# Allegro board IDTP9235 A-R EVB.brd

Outline 40 x 65 mm; copper layers: TOP, TOP_1, BOTTOM. Coordinates in mm from the lower left corner of the outline.
Outline path: 0,65 40,65 40,0 0,0 0,65

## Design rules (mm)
nets with their own width: min track width 0.102; nets GND_POWER

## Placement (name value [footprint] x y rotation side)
A4  PTH_TP  [TP_40]  38.44 7.71 0 top
B2  PTH_TP  [TP_40]  38.44 10.25 0 top
B3  PTH_TP  [TP_40]  38.44 12.79 0 top
BUZ  PTH_TP  [TP_40]  38.44 17.87 0 top
C1  22nF  [0402]  15.02 16.04 180 top
C2  1uF  [0402]  13.47 14.87 180 top
C3  220pF  [0402]  15.38 17.36 90 top
C4  220pF  [0402]  17.17 16.29 0 top
C5  5.6nF  [0402]  13.22 17.36 270 top
C6  6.8nF  [0402]  18.48 16.74 270 top
C7  1uF/10V  [0402]  12.89 2.2 0 top
C8  10uF/10V  [0402]  21.17 16.75 90 top
C9  0.1uF  [0402]  20.3 16.73 90 top
C10  10uF/10V  [0603]  28.55 21.1 0 top
C11  10uF/10V  [0603]  28.46 15.89 0 top
C12  0.1uF  [0402]  28.84 19.75 0 top
C13  0.1uF  [0402]  16.37 7.86 180 top
C14  1uF  [0402]  16.57 14.06 270 top
C15  100nF/50V  [1206]  11.26 20.92 90 top
C16  100nF  [0402]  22.62 16.02 0 top
C17  100nF/50V  [1206]  14.11 20.89 90 top
C18  0.1uF  [0402]  16.57 12.35 90 top
C19  10uF  [0603]  15.1 12.36 90 top
C20  0.1uF  [0402]  13.14 7.81 180 top
C21  10uF  [0603]  12.99 8.98 180 top
C22  NP  [0402]  28.84 17.92 180 top
C23  100nF/50V  [1206]  16.98 20.92 90 top
C24  22nF/25V  [0402]  26.05 19.77 0 top
C25  100nF/50V  [1206]  19.8 20.94 90 top
C26  100nF  [0402]  26.6 12.41 90 top
C27  1uF  [0402]  16.39 10.63 180 top
C28  0.1uF  [0402]  16.37 8.8 180 top
C29  1uF  [0402]  16.37 9.72 180 top
C30  10uF  [0603]  28.46 14.62 0 top
C31  0.1uF  [0402]  28.84 17.01 0 top
C32  NP  [0402]  27.99 22.31 0 top
C33  22nF/25V  [0402]  27.21 24.32 180 top
C34  0.1uF  [0402]  29.14 10.68 90 top
C35  NP  [0402]  20.71 18.02 180 top
C36  NP  [0402]  22.44 22.39 180 top
D1  CMOD3003  [SOD523PD]  10.91 16.6 270 top
D2  LED  [0603_DIODE]  25.66 4.05 270 top
D3  LED  [0603_DIODE]  29.14 4.08 270 top
ENB  PTH_TP  [TP_40]  1.52 15.35 0 top
GND  PTH_TP  [TP_40]  14.36 3.93 0 top
GND1  PTH_TP  [TP_40]  1.52 10.27 0 top
GND2  PTH_TP  [TP_40]  38.44 2.63 0 top
GND3  PTH_TP  [TP_40]  38.44 20.41 0 top
GND_TS  28AWG  [25MIL_TH]  27.92 13.02 0 top
ISNS1  PTH_TP  [28MIL_SMD]  12.08 12.89 0 top
ISNS2  PTH_TP  [28MIL_SMD]  10.73 9.49 0 top
ISNS_IN  PTH_TP  [TP_40]  1.52 20.43 0 top
J1  5P  [USB_MICRO_AB]  20 1.33 0 top
L1  4.7uH  [0603]  12.96 10.28 0 top
L2_1  PTH_TP  [40MIL_50PAD]  22.74 24.07 0 top
L2_2  PTH_TP  [40MIL_50PAD]  15.58 24.14 0 top
LDO18  PTH_TP  [TP_40]  38.42 5.2 0 top
LDO33  PTH_TP  [TP_40]  1.52 2.65 0 top
NOREF  -  []  40 25.01 0 top
NOREF#2  -  [unnamed#2]  38.48 23.48 0 top
NOREF#3  -  []  -116.58 -147.48 0 top
NOREF#4  -  [unnamed#2]  34.67 1.52 0 top
NOREF#5  -  []  30.51 0 0 top
NOREF#6  -  [unnamed#2]  1.52 23.48 0 top
NOREF#7  -  []  0 65 0 top
NOREF#8  -  []  9.49 0.08 0 top
NOREF#9  -  []  0.31 0 90 top
NOREF#10  -  []  0 0 90 top
NOREF#11  -  []  9.48 0 0 top
Q1  FDC654P/SOT23-6  [FDC654P]  11.77 4.99 180 top
Q2  AON7810  [DFN_3X3_DUAL_6LD]  25.26 17.49 270 top
Q3  AON7810  [DFN_3X3_DUAL_6LD]  25.23 22.09 270 top
R1  10k  [0402]  14.23 17.36 270 top
R2  1k  [0402]  17.17 17.39 180 top
R3  220k  [0402]  12.2 17.36 270 top
R4  10  [0402]  13.78 13.5 270 top
R5  10  [0402]  12.84 13.5 90 top
R6  0.02  [0603]  11.03 11.9 90 top
R7  100k  [0402]  11.11 2.2 0 top
R8  1K  [0402]  15.2 14.11 180 top
R9  12  [0402]  22.62 16.88 180 top
R10  NP  [0402]  22.49 18.02 0 top
R11  0  [0402]  24.29 19.77 180 top
R12  12  [0402]  24.72 13.75 270 top
R13  100k  [0402]  28.84 18.86 180 top
R14  12  [0402]  22.44 20.61 180 top
R15  NP  [0402]  22.44 21.53 0 top
R16  12  [0402]  25.64 13.75 270 top
R17  5.1k  [0402]  12.77 16.05 0 top
R18  0  [0402]  25.46 24.32 180 top
R19  100k  [0402]  27.99 23.28 0 top
R20  10k  [0402]  29.14 8.88 270 top
R21  100  [0402]  26.71 9.89 270 top
R22  1K  [0402]  26.81 3.8 90 top
R23  680  [0402]  28 3.77 90 top
R24  NP  [0402]  21.98 6.47 270 top
R25  NP  [0402]  21.09 6.47 270 top
R26  NP  [0402]  24.62 6.47 270 top
R27  NP  [0402]  25.49 6.47 270 top
R28  47k  [0402]  22.87 6.47 90 top
R29  47k  [0402]  20.23 6.47 90 top
R30  47k  [0402]  23.76 6.47 90 top
R31  47k  [0402]  26.35 6.47 90 top
RT1  THERMISTOR 2  [0603]  27.9 10.61 90 top
SCL  PTH_TP  [TP_40]  1.52 5.19 0 top
SDA  PTH_TP  [TP_40]  1.52 7.73 0 top
SS1  Solder_Jumper  [SS3]  13.07 11.65 0 top
TS  PTH_TP  [TP_40]  38.44 15.33 0 top
TS1  28AWG  [25MIL_TH]  27.95 8.24 0 top
U1  P9235A-R  [QFN_40LD_5X5MM_3P75THERM]  20.84 11.88 0 top
VIN_5V  PTH_TP  [TP_40]  1.52 12.81 0 top
VIN_USB  PTH_TP  [TP_40]  14.36 6.47 0 top
VSNS_IN  PTH_TP  [TP_40]  1.52 17.89 0 top

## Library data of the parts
A4 B2 B3 BUZ ENB GND GND1-GND3 ISNS1 ISNS2 ISNS_IN L2_1 L2_2 LDO18 LDO33 SCL SDA TS VIN_5V VIN_USB VSNS_IN = PTH_TP
C1 C5 = C
C2-C4 C6-C36 = CAP NP
D1 = DIODE_1
D2 D3 = LED_0
GND_TS TS1 = PTH
J1 = MICRO USB AB_5
L1 = INDUCTOR
Q1 = IRF6215/TO_2
Q2 Q3 = DMG7430LFG_0
R1-R31 = RESISTOR
RT1 = THERMISTOR 2
SS1 = SolderShort_0
U1 = IDTP9235_7

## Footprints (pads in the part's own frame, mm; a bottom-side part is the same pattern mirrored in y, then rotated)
25MIL_TH
  round 0.889 hole 0.635: 1(0,0)
28MIL_SMD
  round 0.711 smd: 1(0,0)
40MIL_50PAD
  round 1.27 hole 1.016: 1(0,0)
0402
  rect 0.61x0.61 smd: 1(-0.445,0) 2(0.445,0)
0603
  rect 0.635x0.889 smd: 1(-0.762,0) 2(0.762,0)
0603_DIODE
  rect 0.8x0.8 smd: 1(-0.8,0) 2(0.8,0)
1206
  rect 1.4x1.6 smd: 1(-1.5,0) 2(1.5,0)
DFN_3X3_DUAL_6LD
  custom 0.369x0.369 smd: 1(0.859,0.537) 4(-0.859,-0.537)
  rect 0.4x0.58 smd: 2(-0.328,1.36) 3(-0.978,1.36) 5(0.328,-1.36) 6(0.978,-1.36)
FDC654P
  rect 0.7x1 smd: 1(0.95,1.3) 2(0,1.3) 3(-0.95,1.3) 4(-0.95,-1.3) 5(0,-1.3) 6(0.95,-1.3)
QFN_40LD_5X5MM_3P75THERM
  custom 0.062x0.062 smd: 1(-2.418,1.8) 2(-2.418,1.4) 3(-2.418,1) 4(-2.418,0.6) 5(-2.418,0.2) 6(-2.418,-0.2) 7(-2.418,-0.6) 8(-2.418,-1) 9(-2.418,-1.4) 10(-2.418,-1.8) 11(-1.8,-2.418) 12(-1.4,-2.418) 13(-1,-2.418) 14(-0.6,-2.418) 15(-0.2,-2.418) 16(0.2,-2.418) 17(0.6,-2.418) 18(1,-2.418) 19(1.4,-2.418) 20(1.8,-2.418) 21(2.418,-1.8) 22(2.418,-1.4) 23(2.418,-1) 24(2.418,-0.6) 25(2.418,-0.2) 26(2.418,0.2) 27(2.418,0.6) 28(2.418,1) 29(2.418,1.4) 30(2.418,1.8) 31(1.8,2.418) 32(1.4,2.418) 33(1,2.418) 34(0.6,2.418) 35(0.2,2.418) 36(-0.2,2.418) 37(-0.6,2.418) 38(-1,2.418) 39(-1.4,2.418) 40(-1.8,2.418)
  rect 3.75x3.75 smd: 41(0,0)
SOD523PD
  rect 0.8x0.6 smd: 1(-0.55,0) 2(0.55,0)
SS3
  rect 0.254x0.254 smd: 1(-0.889,0) 2(0.889,0)
TP_40
  round 1.524 hole 1.016: 1(0,0)
unnamed#2
  round 1.016 smd: (0,0)
USB_MICRO_AB
  rect 0.4x1.35 smd: 1(-1.3,2.8) 2(-0.65,2.8) 3(0,2.8) 4(0.65,2.8) 5(1.3,2.8)
  oval 1.05x1.25 hole 0.65x0.85: 6(-2.225,3.125) 7(2.225,3.125)
  rect 2.1x1.9 hole 1.5x0.825: 8(4.087,0) 9(-4.087,0)
  rect 1.8x1.9 smd: 10(-1.15,0) 11(1.15,0)

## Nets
GND_POWER: C3.2 C4.1 C5.1 C8.2 C9.2 C10.2 C11.2 C12.2 C13.2 C14.1 C18.1 C19.1 C20.1 C21.1 C22.1 C24.2 C27.2 C28.2 C29.2 C30.2 C31.2 C32.1 C33.1 C34.2 GND.1 GND1.1 GND2.1 GND3.1 GND_TS.1 J1.5 J1.6 J1.7 J1.8 J1.9 J1.10 J1.11(SHIELD) Q2.2(S2) Q3.2(S2) R3.1 R7.1 R8.1 R13.1 R19.1 R28.1 R29.1 R30.1 R31.1 RT1.2 U1.2(GND_S) U1.6(GND_B) U1.28(GND_BRG) U1.35(VSNS_GND) U1.41(EPGND)
VIN_5V: C18.2 C19.2 ISNS2.1 Q1.1 Q1.2 Q1.5 Q1.6 R4.2 R6.1 SS1.2 U1.4(VIN) VIN_5V.1
VIN_LDO: C8.1 C20.2 C21.2 L1.1 SS1.1 U1.8(VIN_LDO) U1.33(VIN_DRV)
VIN_USB: C7.2 C13.1 J1.1 Q1.4 VIN_USB.1
A4: A4.1 U1.17(GPIOA4)
B2: B2.1 U1.22(GPIOB2)
B3: B3.1 U1.23(GPIOB3)
BUZ: R21.2 U1.19(BUZ)
BUZ_TP: BUZ.1 R21.1
ENB: ENB.1 R8.2 U1.1(ENB)
ILIM: R26.1 R30.2 U1.15(ILIM)
ISNS_H: C2.1 R4.1 U1.40(ISNS_H)
ISNS_IN: C6.2 ISNS_IN.1 U1.37(ISNS_IN)
ISNS_L: C2.2 R5.2 U1.39(ISNS_L)
LDO18: C28.1 C29.1 LDO18.1 R24.2 R25.2 R26.2 R27.2 U1.9(VO_18)
LDO33: C27.1 D2.1(ANODE) D3.1(ANODE) LDO33.1 R20.2 U1.7(VO_33) U1.12(VDDIO)
LED_GRN: R23.2 U1.21(LED_GRN)
LED_PAT: R27.1 R31.2 U1.16(LED_PAT)
LED_RED: R22.2 U1.20(LED_RED)
RSVD1: R24.1 R28.2 U1.10(RSVD1)
RSVD2: R25.1 R29.2 U1.11(RSVD2)
SCL: SCL.1 U1.13(SCL)
SDA: SDA.1 U1.14(SDA)
TS: C34.1 R20.1 RT1.1 TS.1 TS1.1 U1.18(TS)
V_BRIDGE: C9.1 C10.1 C11.1 C12.1 C30.1 C31.1 ISNS1.1 Q2.1(D1) Q3.1(D1) R5.1 R6.2 U1.34(VBRG_IN)
VSNS: C5.2 R1.2 R3.2 R17.2
VSNS_IN: C1.1 C3.1 U1.36(VSNS_IN) VSNS_IN.1
N10945: C16.1 U1.31(BST_BRG1)
N10949: C15.1 C16.2 C17.1 C23.1 C25.1 C35.2 Q2.4(D2) Q2.5(S1) R10.2 R11.2 U1.30(SW_BRG1)
N15418: C14.2 U1.3(VO_5)
N61520: C4.2 R2.2 U1.38(ISNS_OUT)
N85909: C26.2 C36.2 L2_1.1 Q3.4(D2) Q3.5(S1) R15.1 R18.2 U1.26(SW_BRG2)
N315180: L1.2 U1.5(SW_B)
N330742: C1.2 R1.1
N332949: C32.2 Q3.3(G2) R16.1 R19.2
N337526: C22.2 Q2.3(G2) R12.1 R13.2
N368946: C15.2 C17.2 C23.2 C25.2 D1.1(A) L2_2.1
N369446: C36.1 Q3.6(G1) R14.1 R15.2
N411524: R9.2 U1.32(GH_BRG1)
N411528: R12.2 U1.29(GL_BRG1)
N411540: R14.2 U1.24(GH_BRG2)
N412617: R16.2 U1.27(GL_BRG2)
N412738: C26.1 U1.25(BST_BRG2)
N417086: C24.1 R11.1
N429702: C33.2 R18.1
N534596: D1.2(C) R17.1
N558172: D2.2(CATHODE) R22.1
N558182: D3.2(CATHODE) R23.1
N579644: C35.1 Q2.6(G1) R9.1 R10.1
N602902: C6.1 R2.1
N8105676: C7.1 Q1.3 R7.2

Pads without a net: J1 2 3 4

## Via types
v1: diameter 0.406, hole 0.203, TOP to BOTTOM, 104 vias
v2: diameter 0.508, hole 0.254, TOP to BOTTOM, 12 vias

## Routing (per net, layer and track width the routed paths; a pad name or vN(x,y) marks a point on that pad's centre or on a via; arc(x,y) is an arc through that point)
GND_POWER: length 22.2
  TOP w0.152: U1.35 21.04,14.65 19.49,16.19 19.49,16.29
  TOP w0.203: v1(19.54,17.03) 19.49,17.08 19.49,17.69 18.98,18.2 16.04,18.2 15.89,18.05 15.62,18.05 C3.2
  TOP w0.254: C8.2 21.14,17.17 v1(20.61,17.17) C9.2 19.68,17.17 v1(19.54,17.03) 19.49,16.98 19.49,16.29 ; v1(29.61,18.86) R13.1 ; C5.1 v1(12.71,17.81) R3.1 ; v1(29.61,17.01) C31.2 ; C3.2 v1(15.38,18.15) ; 19.44,13.28 U1.2 17.89,13.28 17.56,13.6 17.56,14.01 17.07,14.5 C14.1 16.04,14.5 R8.1 ; 20.41,11.68 U1.6 16.8,11.68 C18.1 ; v1(29.61,19.75) C12.2 ; v1(29.61,17.92) C22.1 ; U1.28 v1(23.89,12.87)
  vias: v1(14.29,7.86) v1(14.82,10.61) v1(15.43,10.61) v1(15.45,8.9) v1(15.45,7.86) v1(16.09,11.37) v1(16.72,16.29) v1(18.85,1.33) v1(20.28,7.66) v1(21.15,1.33) v1(25.74,10.3) v1(26.4,6.01) v1(26.49,19.77) v1(27.34,18.8) v1(27.34,18.23) v1(27.34,17.67) v1(27.54,23.38) v1(27.54,22.8) v1(27.54,22.24) v1(27.66,24.32) v1(29.22,15.89) v1(29.22,14.62) v1(29.25,13.63) v1(29.31,21.1) v1(29.3,12.79) v1(29.3,12) v2(19.35,12.49) v2(19.35,11.47) v2(19.35,10.46) v2(20.37,12.49) v2(20.37,11.47) v2(20.37,10.46) v2(21.38,12.49) v2(21.38,11.47) v2(21.38,10.46) v2(22.4,12.49) v2(22.4,11.47) v2(22.4,10.46)
VIN_5V: length 24.2
  TOP w0.254: v1(15.1,13.12) 15.86,13.12 16.18,12.79 C18.2 17.25,12.79 17.57,12.48 U1.4
  TOP w0.508: VIN_5V.1 3.78,10.55 v1(8.44,10.55)
  BOTTOM w0.152: v1(13.78,12.99) 13.14,12.76 11.29,12.76 10.81,12.28 10.81,11.29 10.96,11.14 v1(11.06,11.14)
  BOTTOM w0.254: v1(15.1,13.12) 14.51,13.12 13.78,12.38 11.39,12.38 11.14,12.13 11.14,11.21 v1(11.06,11.14)
  BOTTOM w0.508: v1(8.44,10.55) 10.48,10.55 v1(11.06,11.14)
VIN_LDO: length 26.3
  TOP w0.203: U1.33 21.84,14.89 21,15.72 21,15.98 v1(21.02,15.99) ; U1.8 17.78,10.88 v1(17.64,10.83)
  TOP w0.254: v1(21.02,15.99) 21.02,16.28 C8.1 ; v1(10.3,15.48) 10.3,12.28 10.27,12.25 10.78,11.75 12.08,11.75 SS1.1
  BOTTOM w0.203: 17.11,11.19 17.46,10.83 v1(17.64,10.83)
  BOTTOM w0.254: v1(10.3,15.48) 10.55,15.74 19.03,15.74 19.24,15.53 20.53,15.53 20.99,15.99 v1(21.02,15.99) ; v1(12.23,8.95) 14.49,8.95 16.72,11.19 17.11,11.19
VIN_USB: length 4.4
  TOP w0.254: Q1.4 12.72,5.57 13.35,4.94 13.35,2.46 C7.2
A4: length 22.4
  TOP w0.127: U1.17 21.44,8.99 22.51,7.91 23.68,7.91 23.94,7.66 25.33,7.66 v1(25.46,7.56) ; v1(31.28,4.1) 35.52,4.1 38.44,7.02 A4.1
  BOTTOM w0.127: v1(31.28,4.1) 27.09,4.1 25.69,5.5 25.69,7.3 v1(25.46,7.56)
B2: length 18
  TOP w0.127: B2.1 38.07,10.25 34.8,6.97 v1(31.3,6.97)
  TOP w0.203: U1.22 24.12,10.48 25.89,8.7 v1(25.89,8.62)
  BOTTOM w0.127: v1(31.3,6.97) 31.13,7.15 27.37,7.15 v1(25.89,8.62)
B3: length 19.5
  TOP w0.127: B3.1 38.44,11.98 34.05,7.58 31.3,7.58 v1(31.28,7.61)
  TOP w0.203: U1.23 23.3,10.83 24.32,10.83 26.48,8.67 v1(26.55,8.67)
  BOTTOM w0.127: v1(26.55,8.67) 26.55,8.5 27.65,7.4 31.07,7.4 v1(31.28,7.61)
BUZ: length 6.8
  TOP w0.127: R21.2 26.87,9.45 26.96,9.36 26.96,8.47 26.71,8.22 24.19,8.22 23.99,8.42 22.84,8.42 22.18,9.08 22.18,9.4 U1.19
BUZ_TP: length 15.4
  TOP w0.127: BUZ.1 38.44,16.85 32.17,10.58 v1(31.3,10.58)
  BOTTOM w0.127: v1(31.3,10.58) 26.96,10.58 v1(26.73,10.35)
  vias: v1(26.73,11.11)
ENB: length 19.2
  TOP w0.127: R8.2 14.74,14.12 14.74,14.49 14.87,14.62 15.63,14.62 16.01,15 17.38,15 18.2,14.19 18.2,13.8 18.32,13.68 U1.1 ; v1(8.42,13.58) 3.29,13.58 ENB.1
  BOTTOM w0.127: v1(14.77,14.09) 14.26,13.58 v1(8.42,13.58)
ILIM: length 5.4
  TOP w0.127: U1.15 20.69,9.41 20.69,8.93 22.21,7.4 23.4,7.4 23.76,7.05 R30.2
  TOP w0.254: R30.2 R26.1
ISNS_H: length 6.1
  TOP w0.127: U1.40 19.04,14.59 18.35,15.28 13.75,15.28 13.68,15.2 13.68,15.13
ISNS_IN: length 21.9
  TOP w0.127: v1(8.39,17.13) 4.82,17.13 ISNS_IN.1 ; v1(18.48,16.29) 18.55,16.29 20.24,14.61 U1.37
  BOTTOM w0.127: v1(8.39,17.13) 14.34,17.13 14.87,17.67 17.1,17.67 v1(18.48,16.29)
ISNS_L: length 7.1
  TOP w0.127: U1.39 19.44,14.62 18.53,15.53 13.55,15.53 13.29,15.28 13.29,15.14
LDO18: length 35.1
  TOP w0.127: C28.1 16.92,8.8 17.41,8.31 17.41,7.61 18.41,6.61 v1(18.5,6.44)
  TOP w0.203: C29.1 17.16,9.72 17.91,10.48 U1.9
  TOP w0.254: C29.1 C28.1 ; R24.2 R25.2 ; v1(31.28,3.14) 36.36,3.14 LDO18.1
  BOTTOM w0.127: 19.57,5.96 19.21,5.96 v1(18.5,6.44) ; 19.57,5.96 21.04,5.96 v1(21.07,5.98) ; 19.57,5.96 19.57,3.09 19.7,2.96 24.85,2.96 25.05,3.16
  BOTTOM w0.254: v1(25.05,5.98) 25.05,3.16 25.08,3.14 v1(31.28,3.14)
LDO33: length 52
  TOP w0.203: v1(19.42,8.78) 19.44,8.8 U1.12 ; C27.1 16.85,10.64 16.85,10.99 17.14,11.28 U1.7 ; v1(18.73,6.92) 18.6,6.92 17.71,7.81 v1(17.71,8.88)
  TOP w0.254: 27.42,5.4 28.62,5.4 D3.1 29.32,5.06 29.32,8.26 R20.2 ; 27.42,5.4 v1(27.42,2.58) ; 27.42,5.4 26.21,5.4 D2.1 ; v1(8.47,1.26) 3.9,1.26 2.51,2.65 LDO33.1
  BOTTOM w0.203: v1(16.85,10.61) 17.71,9.74 v1(17.71,8.88) 17.92,8.67 19.31,8.67 v1(19.42,8.78)
  BOTTOM w0.254: v1(8.47,1.26) 13.88,1.26 15.25,2.63 15.28,2.6 19.21,2.6 ; v1(18.73,6.92) 18.3,6.92 17.99,6.62 17.99,6.29 19.21,5.07 19.21,2.6 ; 19.21,2.6 27.29,2.6 v1(27.42,2.58)
LED_GRN: length 8.3
  TOP w0.203: v1(25.31,8.62) 25.31,8.78 24.01,10.08 U1.21
  TOP w0.254: v1(28,4.92) R23.2
  BOTTOM w0.127: v1(28,4.92) 27.95,5.07 26.96,6.06 26.96,6.82 26.96,7 25.33,8.62 v1(25.31,8.62)
LED_PAT: length 6.7
  TOP w0.127: U1.16 21.04,8.98 22.36,7.66 23.56,7.66 23.81,7.4 25.03,7.4 25.49,6.95 R27.1
  TOP w0.254: R27.1 R31.2
LED_RED: length 8.3
  TOP w0.127: U1.20 22.64,9.01 22.97,8.67 24.72,8.67 v1(24.78,8.62)
  TOP w0.254: v1(26.91,4.84) 26.91,4.34 R22.2
  BOTTOM w0.127: v1(24.78,8.62) 25.36,7.96 25.61,7.96 25.94,7.63 25.94,5.63 26.76,4.81 v1(26.91,4.84)
RSVD1: length 8
  TOP w0.127: v1(19.37,6.49) 19.37,6.85 18.25,7.96
  TOP w0.203: U1.10 18.25,9.9 18.25,7.96
  TOP w0.254: R24.1 R28.2
  BOTTOM w0.127: v1(21.98,6.95) 21.42,6.39 20.69,6.39 20.56,6.26 19.59,6.26 v1(19.37,6.49)
RSVD2: length 4.6
  TOP w0.127: U1.11 19.04,9.01 18.63,8.6 18.63,7.96 19.68,6.91 R29.2
  TOP w0.254: R25.1 R29.2
SCL: length 29.2
  TOP w0.127: v1(8.46,1.85) 5.26,1.85 1.92,5.19 SCL.1
  TOP w0.203: U1.13 19.87,9.42 19.87,8.55 19.29,7.96 v1(19.21,7.96)
  BOTTOM w0.127: v1(8.46,1.85) 8.72,1.59 13.75,1.59 15.12,2.96 18.53,2.96 18.86,3.29 18.86,4.97 17.74,6.08 17.41,6.08 17,6.49 17,7.74 17.38,8.12 19.06,8.12 v1(19.21,7.96)
SDA: length 30.5
  TOP w0.127: v1(8.47,2.45) 6.8,2.45 SDA.1
  TOP w0.203: U1.14 20.24,8.36 v1(20.28,8.32)
  BOTTOM w0.127: v1(20.28,8.32) 20.23,8.37 17.23,8.37 16.75,7.89 16.75,6.34 17.26,5.83 17.61,5.83 18.6,4.84 18.6,3.42 18.4,3.21 15,3.21 13.62,1.84 9.08,1.84 v1(8.47,2.45)
TS: length 20.2
  TOP w0.127: RT1.1 27.42,9.84 27.21,9.64 27.21,8.32 26.86,7.96 24.04,7.96 23.84,8.17 22.67,8.17 21.84,9 U1.18 ; TS.1 38.44,15.18 33.21,9.94 v1(31.38,9.94)
  BOTTOM w0.127: v1(31.38,9.94) 31.35,9.94 31.02,10.28 29.3,10.28 v1(29.19,10.17)
V_BRIDGE: length 7.9
  TOP w0.203: U1.34 21.44,14.81 20.38,15.86 ; C9.1 v1(20.3,16.23)
  TOP w0.254: C9.1 20.38,16.21 20.38,15.86
  BOTTOM w0.203: 21.45,14.75 21.47,14.77 21.47,16.17 21.17,16.47 20.75,16.47 20.69,16.35 v1(20.3,16.23)
  BOTTOM w0.254: v1(23.81,15.23) 23.35,14.77 21.47,14.77
  vias: v1(10.83,14.19) v1(10.98,15.13) v1(11.29,14.57) v1(11.72,15.1) v1(23.81,15.79) v1(24.39,15.79) v1(24.37,15.23)
VSNS: length 2.9
  TOP w0.203: R3.2 C5.2 ; C5.2 R17.2 ; C5.2 R1.2
VSNS_IN: length 25
  TOP w0.127: U1.36 20.58,14.35 20.58,14.67 19.09,16.17 19.09,17.64 18.83,17.9 16.22,17.9 16.09,17.77 16.09,17.12 v1(15.89,16.92) ; v1(8.44,16.27) 3.14,16.27 VSNS_IN.1
  TOP w0.203: C1.1 15.38,16.08 C3.1 v1(15.89,16.92)
  BOTTOM w0.127: v1(8.44,16.27) 8.65,16.07 15.03,16.07 v1(15.89,16.92)
N10945: length 2.2
  TOP w0.203: U1.31 22.64,15.28 22.16,15.76 22.16,16.13 C16.1
N10949: length 6.2
  TOP w0.203: v1(23.06,16.02) 23.12,16.05 23.12,13.81 U1.30 ; C35.2 20.27,18.97 C25.1
  BOTTOM w0.254: v1(23.06,16.02) 23.06,17.97 v1(22.95,18.09)
N15418: length 2.2
  TOP w0.203: C14.2 16.61,13.65 16.93,13.65 17.7,12.88 U1.3
N61520: length 5.2
  TOP w0.127: R2.2 16.72,16.96 16.88,16.8 17.43,16.8 17.61,16.63 C4.2 17.61,15.96 17.79,15.79 18.68,15.79 19.84,14.63 U1.38
N85909: length 14
  TOP w0.203: U1.26 25,12.08 25.64,12.71 26.46,12.71 C26.2
  TOP w0.254: C26.2 26.6,13.55 v1(26.53,13.63)
  BOTTOM w0.127: v1(26.53,13.63) 25.94,14.21 25.94,18.25 25.56,18.63 25.56,20.54 24.34,21.76 v1(23.87,21.76)
N315180: length 5.4
  TOP w0.203: v1(17.23,12.15) 17.31,12.08 U1.5
  BOTTOM w0.203: v1(13.73,10.45) 15.6,12.13 15.81,12.13 17.21,12.13 v1(17.23,12.15)
N330742: length 2.3
  TOP w0.127: 14.73,16.43 14.82,16.52
  TOP w0.203: C1.2 14.58,16.28 14.73,16.43 ; 14.82,16.52 14.82,17.56 14.58,17.81 R1.1
N332949: length 14.8
  TOP w0.127: Q3.3 v1(26.59,23.48) 26.92,23.81 28.23,23.81 28.43,23.61 R19.2
  TOP w0.254: v1(26.48,14.24) 26.4,14.31 25.75,14.31 R16.1 ; C32.2 R19.2
  BOTTOM w0.127: v1(26.59,23.48) 26.07,23.48 25.82,23.23 25.82,18.74 26.21,18.34 26.21,14.58 v1(26.48,14.24)
N337526: length 11
  TOP w0.127: C22.2 v1(28.39,18.4) R13.2 ; Q2.3 v1(26.59,19.04) ; 24.72,14.59 24.72,14.49
  TOP w0.254: v1(26.63,14.82) 24.95,14.82 24.72,14.59 ; 24.72,14.49 R12.1
  BOTTOM w0.127: v1(28.39,18.4) 28.39,19 28.03,19.37 26.92,19.37 v1(26.59,19.04) 26.47,18.91 26.47,14.88 v1(26.63,14.82)
N368946: length 6
  TOP w0.127: C15.2 10.25,21.4 ; D1.1 v1(10.91,17.79)
  TOP w0.254: 10.25,21.4 v1(10.25,21.32)
  BOTTOM w0.127: v1(10.25,21.32) 10.2,21.27 10.2,18.5 v1(10.91,17.79)
N369446: length 2.8
  TOP w0.254: 22.88,21.1 R14.1 ; 22.88,21.1 R15.2 C36.1 ; 22.88,21.1 22.9,21.11 Q3.6
N411524: length 3.3
  TOP w0.127: R9.2 22.12,16.93 21.83,16.93 21.68,16.78 21.68,15.58 22.24,15.02 U1.32
N411528: length 1.5
  TOP w0.203: U1.29 23.29,13.31 R12.2
N411540: length 16
  TOP w0.203: v1(24.37,11.27) 24.11,11.28 U1.24 ; v1(21.46,20.56) 21.51,20.61 R14.2
  BOTTOM w0.127: v1(21.46,20.56) 22.2,21.31 24.36,21.31 25.31,20.36 25.31,18.53 25.69,18.15 25.69,12.59 v1(24.37,11.27)
N412617: length 2.8
  TOP w0.203: U1.27 23.3,12.43 24.88,12.43 25.56,13.12 25.56,13.23 R16.2
N412738: length 3.8
  TOP w0.203: U1.25 23.28,11.7 25.11,11.7 25.72,12.31 26.26,12.31 C26.1
N417086: length 0.9
  TOP w0.254: R11.1 C24.1
N429702: length 0.9
  TOP w0.254: R18.1 C33.2
N534596: length 1.4
  TOP w0.127: D1.2 12.33,16.05 R17.1
N558172: length 1.2
  TOP w0.254: D2.2 25.77,3.35 R22.1
N558182: length 1.2
  TOP w0.254: D3.2 29.09,3.33 R23.1
N579644: length 3.8
  TOP w0.203: R10.1 22.03,18.01 22.03,17.67 22.24,17.46 22.8,17.46 23.02,17.28 23.06,17.24 R9.1
  TOP w0.254: Q2.6 23.78,16.63 23.39,16.63 R9.1 ; R10.1 C35.1
N602902: length 0.9
  TOP w0.203: R2.1 18.27,17.39 C6.1
N8105676: length 2.5
  TOP w0.254: R7.2 C7.1 12.44,2.46 12.71,2.73 12.71,3.68 Q1.3

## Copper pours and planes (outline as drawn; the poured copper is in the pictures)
GND_POWER on TOP (solid shape): 19.75,0.35 17.95,0.35 17.95,2.28 19.75,2.28
GND_POWER on TOP (solid shape): 22.05,0.35 20.25,0.35 20.25,2.28 22.05,2.28
GND_POWER on TOP (solid shape): 22.72,10 18.96,10 18.96,13.78 22.72,13.78
GND_POWER on TOP (solid shape): 16.25,2.28 17.4,2.28 17.4,0.35 15.57,0.35 15.57,0.34 15.07,0.34 15.07,2.27 15.1,2.3 16.25,2.3
GND_POWER on TOP (solid shape): 24.83,0.45 24.72,0.34 24.43,0.34 24.43,0.35 22.6,0.35 22.6,2.28 23.75,2.28 23.75,2.3 24.83,2.3
GND_POWER on TOP (solid shape): 27.59,18.99 27.59,17.51 27.47,17.39 27.21,17.39 27.01,17.59 26.3,17.59 26.27,17.62 26.27,18.05 26.3,18.07 27.01,18.07 27.11,18.17 27.11,18.96 27.21,19.06 27.52,19.06
GND_POWER on TOP (solid shape): 27.92,23.61 27.92,22.01 27.87,21.96 27.26,21.96 27.06,22.16 26.3,22.16 26.27,22.19 26.27,22.62 26.3,22.64 26.99,22.64 27.19,22.85 27.19,23.56 27.25,23.62 27.91,23.62
GND_POWER on TOP (solid shape): 29.04,7.61 29.04,5.73 28.99,5.68 26.12,5.68 26.02,5.78 26.02,6.26 26.15,6.39 26.68,6.39 26.77,6.48 26.78,6.48 26.78,6.49 26.96,6.67 26.96,7.63 26.99,7.66 28.99,7.66
GND_POWER on TOP (solid shape): 30.03,24.5 30.03,10.96 29.91,10.83 27.52,10.83 27.34,11.01 27.34,13.42 27.54,13.63 28.8,13.63 28.8,16.26 28.94,16.4 28.94,21.62 28.94,23.58 28.86,23.66 28.86,23.71 28.81,23.71 28.56,23.97 28.35,23.97 28.31,24 27.24,24 27.24,24.6 27.29,24.65 29.88,24.65
GND_POWER on TOP (solid shape): 18.35,4.92 18.35,3.31 16.25,3.31 16.25,2.28 17.4,2.28 17.4,0.35 15.57,0.35 15.57,0.34 10.09,0.34 9.94,0.5 9.94,2.27 10.17,2.5 10.96,2.5 11.01,2.45 11.01,1.87 11.11,1.77 13.76,1.77 13.76,2.63 13.75,2.63 13.75,5.17 13.83,5.25 18.02,5.25
GND_POWER on TOP (solid shape): 26.12,12.05 26.12,9.51 26.1,9.49 25.99,9.49 24.6,10.88 24.57,10.96 24.6,11.03 24.69,11.17 24.69,11.34 24.71,11.43 24.79,11.47 25.21,11.47 25.8,12.07 26.11,12.07
GND_POWER on TOP (solid shape): 21.78,7.4 21.71,7.34 19.8,7.34 19.8,7.33 19.64,7.33 19.49,7.48 19.49,7.76 19.86,8.13 19.94,8.16 20.02,8.12 20.44,8.03 20.59,8.43 20.59,8.44 20.59,8.5 20.69,8.5
GND_POWER on TOP (solid shape): 14.94,12.23 15.1,12.15 15.26,12.23 15.68,12.23 15.68,12.23 16.88,12.23 16.9,12.21 16.9,11.6 16.32,11.6 16.27,11.55 16.27,7.33 16.24,7.31 14.65,7.31 14.64,7.31 14.36,7.35 14.08,7.31 14.07,7.31 13.5,7.31 13.5,7.3 13.45,7.35 13.45,9.44 13.5,9.49 14.34,9.49 14.44,9.59 14.44,10.63 14.26,10.81 14.26,12.21 14.29,12.23
GND_POWER on TOP (solid shape): 24.06,5.7 24.14,5.63 24.19,5.63 24.19,5.59 24.79,5.59 24.8,5.58 24.8,2.38 27.16,2.38 27.42,2.25 27.68,2.38 29.91,2.38 30.03,2.25 30.03,0.52 29.88,0.37 24.8,0.37 24.8,0.34 24.43,0.34 24.43,0.35 22.6,0.35 22.6,2.28 23.75,2.28 23.75,3.31 21.07,3.31 21.05,3.37 21.07,3.39 21.07,4.86 20.76,5.17 20.18,5.17 19.8,5.55 19.8,6.39 19.82,6.41 20.48,6.41 20.48,5.88 20.56,5.8 20.66,5.8 20.66,5.59 22.41,5.59 22.41,6.48 24.06,6.48
GND_POWER on BOTTOM (solid shape): outline of 2845 points within 0.32,0.09 39.58,24.68
VIN_5V on TOP (solid shape): 11.44,11.49 11.49,11.44 11.49,7.71 12.1,7.1 12.1,3.29 10.2,3.29 9.94,3.54 9.94,11.44 9.99,11.49
VIN_5V on TOP (solid shape): 14.16,13.07 14.16,12.29 14.13,12.26 14.13,11.04 14.11,11.01 13.8,11.01 13.8,12.18 13.68,12.31 13.55,12.31 13.42,12.43 13.42,13.15 14.08,13.15
VIN_LDO on TOP (solid shape): 12.38,11.82 12.38,11.29 12.35,11.27 12.35,11.04 12.38,11.01 12.38,10.86 12.58,10.66 12.58,8.4 12.81,8.17 12.96,8.17 12.99,8.14 12.99,7.33 12.94,7.28 12.25,7.28 11.87,7.66 11.87,11.85 11.9,11.88 12.33,11.88
VIN_USB on TOP (solid shape): 17.22,7.53 17.26,7.49 17.26,7.25 18.1,6.41 18.17,6.41 18.18,6.37 18.4,6.13 18.73,6.2 18.76,6.21 18.8,6.2 18.91,6.08 18.91,3.49 18.88,3.47 18.55,3.47 18.5,3.52 18.5,5.02 18.13,5.39 18.12,5.37 12.58,5.37 12.38,5.58 12.38,6.97 12.46,7.05 16.52,7.05 16.52,7.99 16.55,7.99 16.55,8.17 17.22,8.17
(no net) on TOP: 18.55,3.47 18.5,3.52 18.5,5.02 18.13,5.39 18.12,5.37 12.58,5.37 12.38,5.58 12.38,6.97 12.46,7.05 16.52,7.05 16.52,7.99 16.55,7.99 16.55,8.17 17.23,8.17 17.26,8.14 17.26,7.25 18.1,6.41 18.58,6.41 18.91,6.08 18.91,3.49 18.88,3.47
(no net) on TOP: 13.45,9.44 13.45,7.35 13.5,7.3 13.5,7.31 16.24,7.31 16.27,7.33 16.27,11.55 16.32,11.6 16.9,11.6 16.9,12.21 16.88,12.23 15.68,12.23 15.68,12.23 14.29,12.23 14.26,12.21 14.26,10.81 14.44,10.63 14.44,9.59 14.34,9.49 13.5,9.49
(no net) on TOP: 13.8,11.01 14.11,11.01 14.16,11.06 14.16,13.07 14.08,13.15 13.42,13.15 13.42,12.43 13.55,12.31 13.68,12.31 13.8,12.18
(no net) on TOP: 11.44,11.49 9.99,11.49 9.94,11.44 9.94,3.54 10.2,3.29 12.1,3.29 12.1,7.1 11.49,7.71 11.49,11.44
(no net) on TOP: 10.09,0.34 9.94,0.5 9.94,2.27 10.17,2.5 10.96,2.5 11.01,2.45 11.01,1.87 11.11,1.77 13.62,1.77 13.75,1.89 13.75,5.17 13.83,5.25 18.02,5.25 18.35,4.92 18.35,3.37 18.43,3.29 20.97,3.29 21.07,3.39 21.07,4.86 20.76,5.17 20.18,5.17 19.8,5.55 19.8,6.39 19.82,6.41 20.48,6.41 20.48,5.88 20.56,5.8 21.47,5.8 21.47,5.88 22.29,5.88 22.29,6.49 22.39,6.59 23.96,6.59 24.06,6.49 24.06,5.7 24.14,5.63 24.75,5.63 24.8,5.58 24.8,2.38 29.91,2.38 30.03,2.25 30.03,0.52 29.88,0.37 24.8,0.37 24.8,0.34
(no net) on TOP: 26.12,5.68 26.02,5.78 26.02,6.26 26.15,6.39 26.68,6.39 26.96,6.67 26.96,7.63 26.99,7.66 28.99,7.66 29.04,7.61 29.04,5.73 28.99,5.68
(no net) on TOP: 15.1,2.3 24.8,2.3 24.83,2.32 24.83,0.45 24.72,0.34 15.07,0.34 15.07,2.27
(no net) on TOP: 10.58,12.33 10.55,12.36 10.55,15.3 10.73,15.48 11.97,15.48 12.02,15.43 12.02,14.57 11.77,14.31 11.77,13.45 11.87,13.35 13.09,13.35 13.17,13.27 13.17,12.43 13.09,12.36 12.53,12.36 12.51,12.33
(no net) on TOP: 20.94,21.2 20.84,21.3 20.84,24.68 25.33,24.68 25.33,24.03 25.84,23.52 25.84,22.21 25.82,22.19 24.42,22.19 24.24,22.01 24.24,21.58 24.19,21.53 23.56,21.53 23.51,21.58 23.51,22.44 23.33,22.62 22.39,22.62 22.29,22.52 22.29,21.22 22.26,21.22 22.24,21.2
(no net) on TOP: 26.3,18.07 27.01,18.07 27.11,18.17 27.11,18.96 27.21,19.06 27.52,19.06 27.59,18.99 27.59,17.51 27.47,17.39 27.21,17.39 27.01,17.59 26.3,17.59 26.27,17.62 26.27,18.05
(no net) on TOP: 18.96,10 18.96,13.78 22.72,13.78 22.72,10
(no net) on TOP: 27.52,10.83 27.34,11.01 27.34,13.42 27.54,13.63 28.8,13.63 28.8,16.26 28.94,16.4 28.94,21.62 28.94,23.58 28.56,23.97 27.26,23.97 27.24,23.99 27.24,24.6 27.29,24.65 29.88,24.65 30.03,24.5 30.03,10.96 29.91,10.83
(no net) on TOP: 13.6,15.15 13.6,14.67 13.45,14.52 13.45,13.65 13.47,13.63 14.16,13.63 14.23,13.7 14.23,15.13 14.18,15.18 13.62,15.18
(no net) on TOP: 12.56,13.63 12.53,13.65 12.53,14.24 12.74,14.44 12.74,15.23 13.24,15.23 13.35,15.13 13.35,14.54 13.29,14.49 13.29,13.78 13.14,13.63
(no net) on TOP: 26.3,22.64 26.99,22.64 27.19,22.85 27.19,23.56 27.26,23.64 27.9,23.64 27.92,23.61 27.92,22.01 27.87,21.96 27.26,21.96 27.06,22.16 26.3,22.16 26.27,22.19 26.27,22.62
(no net) on TOP: 27.42,7.81 27.34,7.89 27.34,10.35 27.49,10.5 29.86,10.5 30.03,10.33 30.03,9.11 29.93,9.01 28.79,9.01 28.71,8.93 28.71,7.89 28.64,7.81
(no net) on TOP: 23.56,16.96 23.53,16.98 23.53,17.44 23.23,17.74 22.62,17.74 22.62,18.4 22.57,18.45 10.53,18.45 10.4,18.58 10.4,20.92 10.48,20.99 20.53,20.99 21.42,20.1 24.19,20.1 24.19,19.39 24.39,19.19 25.72,19.19 25.84,19.06 25.84,17.64 25.79,17.59 24.29,17.59 24.19,17.49 24.19,16.98 24.17,16.96
(no net) on TOP: 10.48,21.2 10.4,21.27 10.4,24.6 10.48,24.68 20.56,24.68 20.64,24.6 20.64,21.3 20.53,21.2
(no net) on TOP: 26.78,20.38 24.75,20.38 24.6,20.54 24.6,21.96 24.65,22.01 26.88,22.01 27.21,21.68 28.03,21.68 28.13,21.58 28.13,20.64 28.74,20.03 28.74,19.47 28.66,19.39 28.26,19.39 28.13,19.27 28.13,17.49 28.2,17.41 28.66,17.41 28.74,17.34 28.74,16.63 28.64,16.52 28.26,16.52 28.05,16.32 28.05,14.16 28.03,14.14 27.24,14.14 27.21,14.16 27.21,14.92 26.99,15.15 24.88,15.15 24.65,14.92 23.53,14.92 23.48,14.97 23.48,15.99 23.58,16.09 24.29,16.09 24.62,16.42 24.62,17.41 24.65,17.44 26.91,17.44 27.14,17.21 27.67,17.21 27.7,17.23 27.7,19.47
(no net) on TOP: 26.1,9.49 25.99,9.49 24.5,10.99 24.5,11.44 24.52,11.47 25.21,11.47 25.8,12.07 26.11,12.07 26.12,12.05 26.12,9.51
(no net) on TOP: 20.69,8.5 21.78,7.4 21.7,7.33 19.64,7.33 19.49,7.48 19.49,7.76 20.23,8.5
(no net) on TOP: 12.25,7.28 11.87,7.66 11.87,11.85 11.9,11.88 12.33,11.88 12.38,11.82 12.38,10.86 12.58,10.66 12.58,8.4 12.81,8.17 12.96,8.17 12.99,8.14 12.99,7.33 12.94,7.28
(no net) on TOP: 26.3,10.05 26.25,10.1 26.25,11.37 26.3,11.42 27.09,11.42 27.14,11.37 27.14,10.07 27.11,10.05
(no net) on BOTTOM: 10.04,13.86 10.04,15.41 10.14,15.51 18.81,15.51 19.16,15.15 22.77,15.15 23.84,16.22 24.42,16.22 24.65,15.99 24.65,14.95 22.97,13.27 18.35,13.27 17.97,13.65 10.25,13.65
(no net) on BOTTOM: 0.32,0.09 0.32,24.68 39.58,24.68 39.58,0.09 ; 1 cut-out
BUZ_TP on TOP (solid shape): 27.14,11.37 27.14,10.07 27.11,10.05 26.3,10.05 26.25,10.1 26.25,11.37 26.3,11.42 27.09,11.42
ISNS_H on TOP (solid shape): 14.23,15.13 14.23,13.7 14.16,13.63 13.47,13.63 13.45,13.65 13.45,14.44 13.46,14.44 13.46,14.48 13.47,14.49 13.47,14.54 13.6,14.67 13.6,15.15 13.62,15.18 14.18,15.18
ISNS_L on TOP (solid shape): 13.35,15.13 13.35,14.57 13.34,14.56 13.34,14.54 13.29,14.49 13.29,13.78 13.14,13.63 12.56,13.63 12.53,13.65 12.53,14.24 12.74,14.44 12.74,15.23 13.24,15.23
Net_56 on TOP_1 (solid shape): 13.45,12.1 12.58,12.1 12.53,12.05 12.53,11.77 12.58,11.72 13.45,11.72 13.45,11.57 12.58,11.57 12.53,11.52 12.53,11.24 12.58,11.19 13.45,11.19 13.45,11.06 12.38,11.06 12.05,11.39 12.05,11.9 12.38,12.23 13.45,12.23
TS on TOP (solid shape): 27.74,10.48 27.9,10.4 28.06,10.48 28.08,10.5 29.86,10.5 30.03,10.33 30.03,9.11 29.93,9.01 28.79,9.01 28.71,8.93 28.71,7.89 28.64,7.81 27.42,7.81 27.34,7.89 27.34,10.35 27.49,10.5 27.72,10.5
V_BRIDGE on TOP (solid shape): 12.02,15.43 12.02,14.57 11.77,14.31 11.77,13.45 11.87,13.35 13.09,13.35 13.17,13.27 13.17,12.43 13.09,12.36 12.46,12.36 12.43,12.33 10.58,12.33 10.55,12.36 10.55,15.27 10.58,15.31 10.6,15.36 10.73,15.48 11.97,15.48
V_BRIDGE on TOP (solid shape): 27.21,21.68 28.03,21.68 28.13,21.58 28.13,20.64 28.74,20.03 28.74,19.47 28.66,19.39 28.26,19.39 28.15,19.29 27.96,19.29 27.96,17.49 28.13,17.49 28.2,17.41 28.66,17.41 28.74,17.34 28.74,16.63 28.64,16.52 28.26,16.52 28.05,16.32 28.05,14.16 28.03,14.14 27.24,14.14 27.21,14.16 27.21,14.92 26.99,15.15 24.88,15.15 24.65,14.92 23.53,14.92 23.48,14.97 23.48,15.58 23.49,15.58 23.49,16 23.58,16.09 24.29,16.09 24.62,16.42 24.62,17.41 24.65,17.44 26.91,17.44 27.14,17.21 27.67,17.21 27.7,17.23 27.7,17.44 27.72,17.46 27.72,19.04 27.7,19.07 27.7,19.47 26.78,20.38 24.75,20.38 24.6,20.54 24.6,21.96 24.65,22.01 26.88,22.01
V_BRIDGE on BOTTOM (solid shape): 24.65,15.99 24.65,14.95 22.97,13.27 18.35,13.27 17.97,13.65 15.05,13.65 14.95,13.72 14.98,13.83 14.89,14.39 14.44,14.05 14.44,14.03 14.18,13.77 10.13,13.77 10.04,13.86 10.04,15.08 10.09,15.16 10.18,15.17 10.47,15.2 10.62,15.44 10.63,15.45 10.66,15.48 18.83,15.48 19.16,15.15 22.77,15.15 23.84,16.22 24.42,16.22
N10949 on TOP (solid shape): 21.42,20.1 24.19,20.1 24.19,19.39 24.39,19.19 25.72,19.19 25.84,19.06 25.84,17.64 25.79,17.59 24.29,17.59 24.19,17.49 24.19,16.98 24.17,16.96 23.56,16.96 23.53,16.98 23.53,17.44 23.23,17.74 22.62,17.74 22.62,18.4 22.57,18.45 20.72,18.45 15.5,18.45 15.5,18.46 15.38,18.48 15.26,18.46 15.25,18.45 10.53,18.45 10.4,18.58 10.4,20.92 10.48,20.99 20.53,20.99
N85909 on TOP (solid shape): 25.33,24.03 25.84,23.52 25.84,22.21 25.82,22.19 24.42,22.19 24.24,22.01 24.24,21.58 24.19,21.53 23.56,21.53 23.51,21.58 23.51,22.44 23.33,22.62 23.31,22.62 23.31,22.82 22.45,22.82 22.45,22.62 22.39,22.62 22.29,22.52 22.29,21.25 22.24,21.2 20.94,21.2 20.84,21.3 20.84,24.68 25.33,24.68
N368946 on TOP (solid shape): 20.64,24.6 20.64,21.3 20.53,21.2 10.68,21.2 10.6,21.23 10.58,21.3 10.53,21.49 10.4,21.62 10.4,24.6 10.48,24.68 20.56,24.68

Small or netless copper shapes (teardrops, artwork), in the pictures only: 2 on TOP, 2 on BOTTOM, 1 on TOP_1

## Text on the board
BOTTOM: 02_BOTTOM
Board Geometry/Soldermask Bottom: 08_SMASK_BOT
Ref Des/Silkscreen Bottom: 06_SILK_BOT
User.Comments: 305-PD-15-0860 | NOV 2015
TOP: 01_TOP
Ref Des/Assembly Top: BUZ | TS
Board Geometry/Soldermask Top: 07_SMASK_TOP
Package Geometry/Pastemask Top: TOP_PASTE
Ref Des/Silkscreen Top: BUZ | ISNS_IN | VIN_5V | SCL | SDA | L2_2 | GND | VIN_USB | L2_1 | TS | P9235A-R EVK V2 | LDO18 | B3 | B2 | A4 | ENB | LDO33 | VSNS_IN | 05_SILK_TOP
DISPLAY_TOP: TITLE | DATE | LAYOUT | DESIGN | IDTP9235A-R EV BOARD | 03/14/16
BODY_CENTER: 7. SOLDER MASK BOTH SIDES GREEN USING LIQUID PHOTO IMAGEABLE METHOD. | 8. ALL ATWORK MEDIA SHALL BE SUPPLIED BY PACTRON. NO CHANGES WILL BE | 6. ETCH VENDOR ID, UL DESIGNATION AND DATECODE ON THE BACKSIDE. | 10. BOARD TO BE SCORED AT THE LOCATIONS INDICATED | 11. 8 AND 10 MILS HOLE NEED TO BE NON CONDUCTIVE FILLED | 9. BOARD DIMENSIONS ARE IN INCHES [MM]. | SILKSCREEN BOTH SIDES USING EPOXY BASED, WHITE NON-CONDUCTIVE SILKSCREEN. | UNLESS OTHERWISE SPECIFIED. | HOLE DIAMETERS ARE AFTER PLATING, 001 MINIMUM. | TYPE FR4 PER STACKUP DETAIL, OR EQUIVALENT. | NOTE: LEGEND SHOULD BE REMOVED FROM ANY CONDUCTIVE SURFACE | FINISH: LEAD FREE HASL OR EQUIVELENT. | BUILD IN ACCORDANCE WITH IPC 6011 & IPC 6012. CLASS 2. | LAMINATE MATERIAL SHALL MEET THE REQUIREMENTS OF IPC 4101. | ALLOWED WITHOUT SPECIFIC APPROVAL FROM IDT ENGINEERING. | 1. | 2. | 5. | 3. | 4. | NOTES:
User.6: SCALE = NONE | R | 10mil Approx | LAYER #1 TOP SIDE 1.5 OZ ( FINISHED SHOULD BE 1.5 OZ TO 2 OZ) | LAYER #2 BOTTOM SIDE 1.5 OZ ( FINISHED SHOULD BE 1.5 OZ TO 2 OZ) | SCORING REQUIRED ON TOP SIDE ONLY. DO NOT DISCONNECT TRACES ON THE BOTTOM. | BOTTOM SIDE SOLDERMASK | BOTTOM SIDE SILKSCREEN | TOP SIDE SILKSCREEN | TOP SIDE SOLDERMASK | SCORING REQUIRED FROM TOP & BOTTOM.. | +/-3 | 31.5 MILS | VIEW A-A | FAB
User.9: FIGURE | SIZE | 8.0 | 10.0 | 25.0 | 40.0 | 33.465x25.591 | 59.055x32.48 | DRILL CHART: TOP to BOTTOM | ALL UNITS ARE IN MILS | TOLERANCE | +3.0/-3.0 | PLATED | QTY | 104 | 12 | 2 | 18
